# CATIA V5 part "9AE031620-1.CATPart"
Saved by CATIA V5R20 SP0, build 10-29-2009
Part number: 9AE031620-1
Revision: ANY
Definition: UNKNOWN
Nomenclature: 9AE031620-1
Source: Unknown
Bounding box of the stored display mesh (mm): x -9.453 to 3.047, y -22 to 27, z -6.093 to 6.093
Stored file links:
  C:\Users\Utente\Desktop\IO LAVORO\3D X SITO CF\CUMSA\3D files AE\AE 031620\9AE031620-1.CATPart
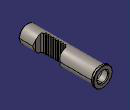
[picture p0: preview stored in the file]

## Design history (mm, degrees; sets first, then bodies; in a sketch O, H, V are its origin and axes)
Body1 "Chaflán1" (main body)
  Solid1: solid without history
